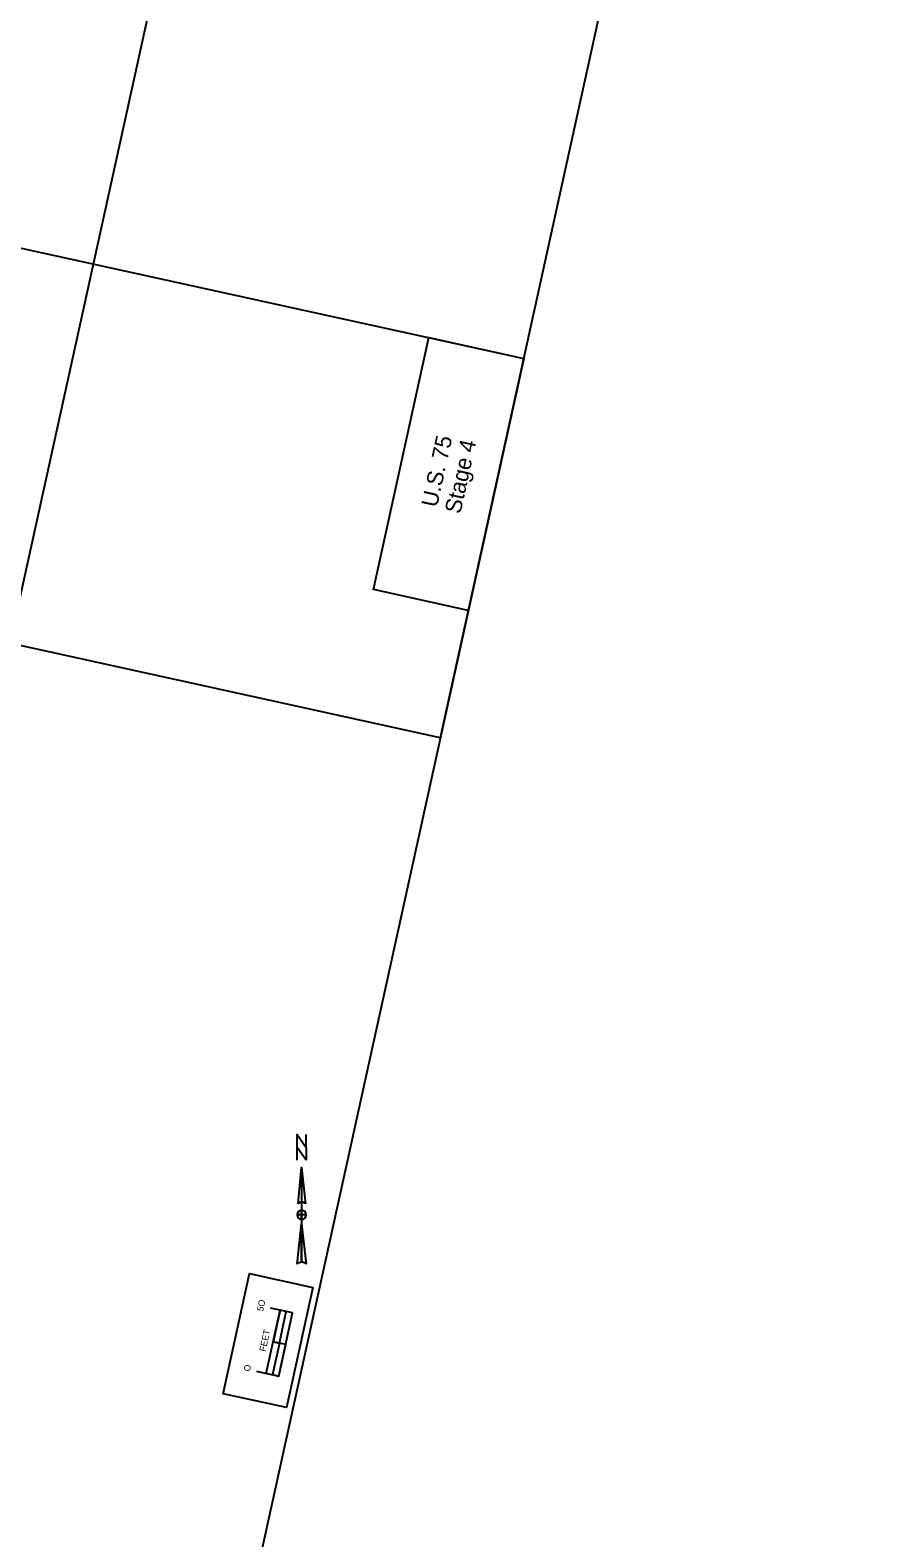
# Model space of a CAD drawing. Extents: x 14104283 to 14120882, y 8635219 to 8671666.
# Drawn here: x 14108160 to 14108813, y 8639045 to 8640210 of the extents above; entities that cross this region are included whole.
import ezdxf

# ---------------------------------------------------------------- set-up
doc = ezdxf.new("R2010")
doc.units = 0
for name, color, linetype in [('dsnCellsNorthArrow', 7, 'Continuous'), ('dsnCellsScaleBlock', 7, 'Continuous'), ('dsnNonPlotable', 7, 'Continuous'), ('dsnTextOverlapEven', 7, 'Continuous')]:
    doc.layers.add(name, color=color, linetype=linetype)

msp = doc.modelspace()

# ---------------------------------------------------------------- linework, layer by layer
at = {"layer": 'dsnCellsNorthArrow'}
for p, q in [((14108369.8, 8639331.3), (14108372.7, 8639303.2)), ((14108369.8, 8639331.3), (14108369.8, 8639258.1)), ((14108367, 8639303.2), (14108367, 8639303.2)), ((14108367.1, 8639303.4), (14108367.7, 8639304)), ((14108366.3, 8639256.7), (14108369.8, 8639287.7)), ((14108369.8, 8639291.2), (14108369.8, 8639291.2))]:
    msp.add_line(p, q, dxfattribs=at)
msp.add_lwpolyline([(14108373.4, 8639337), (14108366.3, 8639346.8), (14108366.3, 8639356.7), (14108373.4, 8639346.8)], close=True, dxfattribs=at)
for points in [[(14108366.3, 8639337), (14108366.3, 8639356.7), (14108373.4, 8639346.8), (14108373.4, 8639356.7)], [(14108367, 8639303.2), (14108369.8, 8639331.3), (14108369.8, 8639304.6)], [(14108373.4, 8639294.7), (14108369.8, 8639294.7), (14108369.8, 8639298.2)], [(14108369.8, 8639291.2), (14108369.8, 8639294.7), (14108366.3, 8639294.7)], [(14108369.8, 8639258.1), (14108369.8, 8639287.7), (14108373.4, 8639256.7)]]:
    msp.add_lwpolyline(points, dxfattribs=at)
for centre, radius, start, end in [((14108369.8, 8639294.7), 3.52, 90, 180), ((14108369.9, 8639301), 3.52, 90.0204, 143.1257), ((14108369.9, 8639301), 3.52, 36.8481, 90.0218), ((14108369.8, 8639294.7), 3.52, 0, 90), ((14108369.8, 8639294.7), 3.52, 180, 270), ((14108369.8, 8639294.7), 3.52, 270, 360), ((14108369.8, 8639253), 5.1, 89.9894, 133.619), ((14108369.8, 8639253), 5.11, 46.4021, 90.0006)]:
    msp.add_arc(centre, radius, start, end, dxfattribs=at)
at = {"layer": 'dsnCellsScaleBlock'}
msp.add_line((14108357.5, 8639194.5), (14108347.7, 8639196.6), dxfattribs=at)
msp.add_line((14108357.5, 8639194.5), (14108347.7, 8639196.6), dxfattribs=at)
for points in [[(14108358, 8639145.7), (14108309.2, 8639156.5), (14108329.6, 8639249.3), (14108378.4, 8639238.5)], [(14108309.2, 8639156.5), (14108329.6, 8639249.3), (14108378.4, 8639238.5), (14108358, 8639145.7)], [(14108358, 8639145.7), (14108309.2, 8639156.5), (14108329.6, 8639249.3), (14108378.4, 8639238.5)], [(14108352.6, 8639195.6), (14108357.9, 8639220), (14108353.1, 8639221.1), (14108347.7, 8639196.6)], [(14108352.1, 8639170.1), (14108357.5, 8639194.5), (14108352.6, 8639195.6), (14108347.2, 8639171.2)]]:
    msp.add_lwpolyline(points, close=True, dxfattribs=at)
for points in [[(14108335, 8639173.8), (14108352.1, 8639170.1), (14108362.8, 8639218.9), (14108345.8, 8639222.7)], [(14108342.3, 8639172.2), (14108353.1, 8639221.1)]]:
    msp.add_lwpolyline(points, dxfattribs=at)
at = {"layer": 'dsnNonPlotable'}
for points in [[(14107490.5, 8639880.3), (14107826.8, 8641411.3), (14108813.3, 8641194.5), (14108476.9, 8639663.5)], [(14107651.3, 8639844.9), (14107987.7, 8641375.9), (14108480.9, 8641267.5), (14108144.5, 8639736.6)], [(14107218.4, 8638642.3), (14107554.8, 8640173.3), (14108541.3, 8639956.6), (14108204.9, 8638425.6)]]:
    msp.add_lwpolyline(points, close=True, dxfattribs=at)
at = {"layer": 'dsnTextOverlapEven'}
for points in [[(14108541.3, 8639956.6), (14108498.5, 8639761.9), (14108425.3, 8639778), (14108468, 8639972.7)], [(14108425.3, 8639778), (14108468, 8639972.7), (14108541.3, 8639956.6), (14108498.5, 8639761.9)]]:
    msp.add_lwpolyline(points, close=True, dxfattribs=at)

# ---------------------------------------------------------------- texts
at = {"layer": 'dsnCellsScaleBlock'}
for s, p in [('5O', (14108340, 8639219.8)), ('FEET', (14108341.9, 8639188.7)), ('O', (14108329.8, 8639173.3))]:
    msp.add_text(s, height=5, rotation=77.6078, dxfattribs=at).set_placement(p)
at = {"layer": 'dsnTextOverlapEven'}
for s, p in [('U.S. 75', (14108474.3, 8639841)), ('Stage 4', (14108492.4, 8639836))]:
    msp.add_text(s, height=12.5, rotation=77.6078, dxfattribs=at).set_placement(p)

doc.saveas('drawing.dxf')
